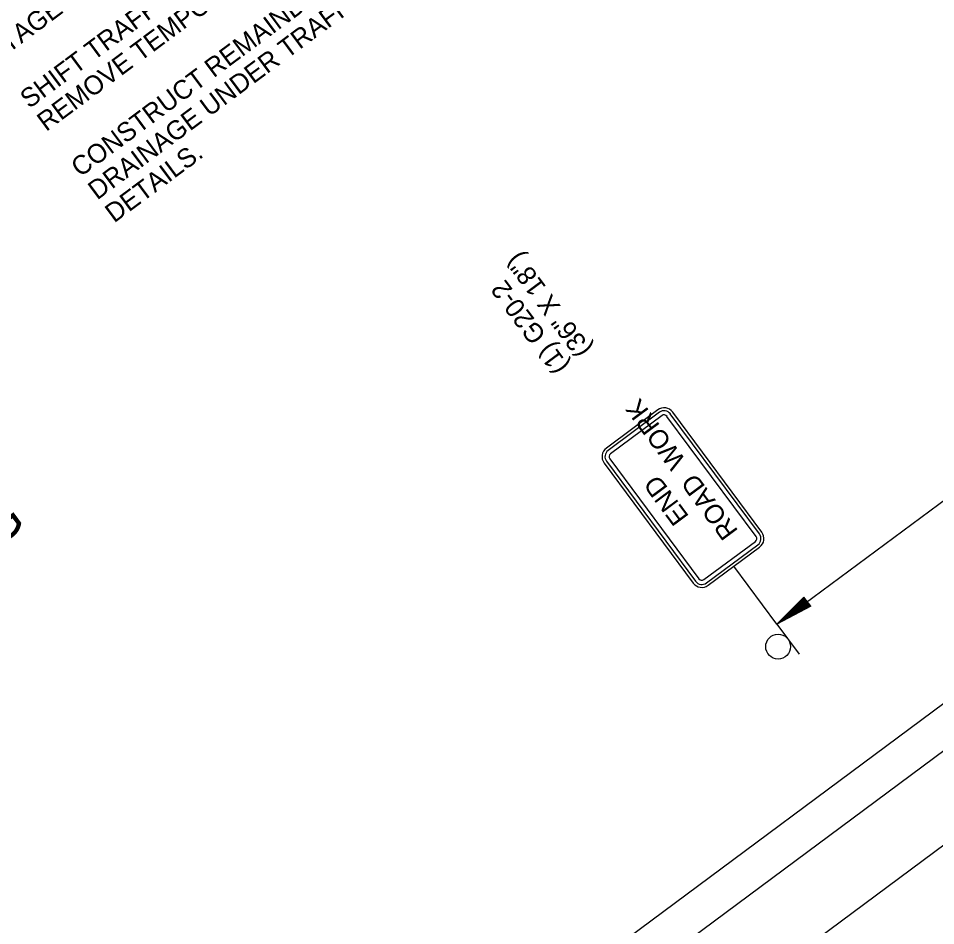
# Model space of a CAD drawing. Extents: x -238 to 1487, y -1123 to 446.
# Drawn here: x 83.5 to 373.5, y -710.5 to -423.8 of the extents above; entities that cross this region are included whole.
import ezdxf

# ---------------------------------------------------------------- set-up
doc = ezdxf.new("R2010")
doc.units = 0
for name, color, linetype in [('P_TC_Signs_Temporary', 7, 'Continuous'), ('R_Border Prem', 7, 'Continuous'), ('R_Draft', 7, 'Continuous'), ('STAMP', 7, 'Continuous')]:
    doc.layers.add(name, color=color, linetype=linetype)

msp = doc.modelspace()

# ---------------------------------------------------------------- linework, layer by layer
at = {"layer": 'P_TC_Signs_Temporary'}
for p, q in [((285.68, -547.52), (269.42, -559.59)), ((286.23, -548.28), (269.98, -560.35)), ((287.02, -549.33), (270.76, -561.4)), ((316.76, -587.5), (288.59, -549.56)), ((317.81, -586.71), (289.64, -548.78)), ((318.57, -586.16), (290.4, -548.22)), ((268.72, -564.32), (296.89, -602.25)), ((269.47, -563.76), (297.64, -601.69)), ((270.53, -562.98), (298.7, -600.91)), ((300.27, -601.14), (316.53, -589.07)), ((301.05, -602.2), (317.31, -590.12)), ((301.61, -602.95), (317.87, -590.88))]:
    msp.add_line(p, q, dxfattribs=at)
for centre, radius, start, end in [((287.69, -550.23), 3.38, 36.5953, 126.5953), ((287.69, -550.23), 2.44, 36.5953, 126.5953), ((287.69, -550.23), 1.13, 36.5953, 126.5953), ((271.43, -562.3), 3.38, 126.5953, 216.5953), ((271.43, -562.3), 2.44, 126.5953, 216.5953), ((271.43, -562.3), 1.13, 126.5953, 216.5953), ((315.86, -588.17), 1.13, 306.5953, 36.5953), ((315.86, -588.17), 2.44, 306.5953, 36.5953), ((315.86, -588.17), 3.38, 306.5953, 36.5953), ((299.6, -600.24), 3.38, 216.5953, 306.5953), ((299.6, -600.24), 2.44, 216.5953, 306.5953), ((299.6, -600.24), 1.13, 216.5953, 306.5953)]:
    msp.add_arc(centre, radius, start, end, dxfattribs=at)
at = {"layer": 'R_Draft'}
for p, q in [((323.36, -615.26), (483.94, -496.03)), ((54.3, -923.87), (605.38, -514.67)), ((32.89, -895.04), (504.89, -544.56)), ((40.03, -904.65), (512.02, -554.17)), ((323.36, -615.26), (309.74, -596.91)), ((331.9, -606.69), (323.36, -615.26)), ((332.08, -606.93), (324.97, -614.07)), ((332.26, -607.17), (326.62, -612.84)), ((332.44, -607.41), (328.22, -611.65)), ((333.51, -608.84), (328.22, -611.65)), ((332.63, -607.66), (329.85, -610.45)), ((333.32, -608.59), (329.85, -610.45)), ((332.81, -607.9), (331.46, -609.25)), ((333.14, -608.35), (331.46, -609.25)), ((334.04, -609.57), (331.9, -606.69)), ((334.04, -609.57), (323.36, -615.26)), ((333.87, -609.33), (324.97, -614.07)), ((333.69, -609.08), (326.62, -612.84))]:
    msp.add_line(p, q, dxfattribs=at)
at = {"layer": 'STAMP'}
msp.add_line((323.36, -615.26), (330.37, -624.7), dxfattribs=at)
msp.add_circle((323.72, -622.32), 3.92, dxfattribs=at)

# ---------------------------------------------------------------- texts
at = {"layer": 'P_TC_Signs_Temporary'}
for s, p in [('ROAD  WORK', (311.27, -585.76)), ('END', (295.73, -581.2))]:
    msp.add_text(s, height=6, rotation=126.5953, dxfattribs=at).set_placement(p)
at = {"layer": 'R_Border Prem'}
for s, height, rotation, p in [('DRAINAGE UNDER TRAFFIC FOR PROJECT AS SHOWN IN STAGE 3 MAINTENANCE OF TRAFFIC', 6, 36.6341, (108.44, -481.38)), ('SHIFT TRAFFIC TO NEWLY CONSTRUCTED ROADWAY AND BOX CULVERT AND ', 6, 36.6341, (86.96, -452.49)), ('CONSTRUCT REMAINDER OF ROADWAY TIES, FINAL OVERLAY, FINAL GRADING, AND ', 6, 36.6341, (103.07, -474.15)), ('REMOVE TEMPORARY PAVEMENT WIDENING. ', 6, 36.6341, (92.33, -459.71)), ('STAGE 3:', 6, 36.6341, (76.22, -438.04)), ('DETAILS. ', 6, 36.6341, (113.82, -488.6)), ('(36" X 18")', 6, 126.5953, (265.06, -528.18)), ('(1) G20-2', 6, 126.5953, (257.83, -533.55)), ('ADVANCE WARNING', 12, 36.5953, (-41.6, -679.12))]:
    msp.add_text(s, height=height, rotation=rotation, dxfattribs=at).set_placement(p)

doc.saveas('drawing.dxf')
